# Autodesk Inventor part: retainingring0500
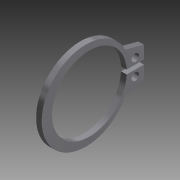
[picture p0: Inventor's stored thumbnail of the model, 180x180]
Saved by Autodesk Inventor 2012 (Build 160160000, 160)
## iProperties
Shininess: 60.0
Created: 2001-12
Part Number: retainingring0500
Material: Steel, High Strength Low Alloy
Document SubType Name: Modeling
Density: 7.84 g/cm^3
Mass: 0.376218 g
Surface Area: 1.94651 cm^2
Volume: 0.047987 cm^3
Density: 0.0
Volumn: 0.0
Area: 0.0
PropertySet Name: Model Information
Control State: 0
Master: False
Checked Out: False
Author: Administrator
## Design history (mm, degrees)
node "Base1"
body "Solid1"
